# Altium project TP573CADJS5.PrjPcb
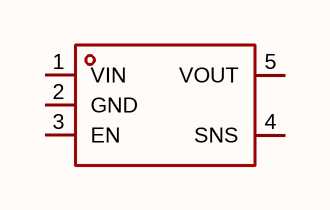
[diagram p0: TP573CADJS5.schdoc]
1 sheet, 1 parts. Net scope: global (net labels, ports and power ports of the same name join across sheets).

## Sheet TP573CADJS5.schdoc
size 127 x 101 mm

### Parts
U?  tp573cadjs5  [SOT-23-5_L2.9-W1.6-P0.95-LS2.8-BR]  (value not drawn)

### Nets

Not connected (* = marked no-connect by the designer): U? 1(VIN) 2(GND) 3(EN) 4(SNS) 5(VOUT)

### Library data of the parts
U? = tp573cadjs5: 输出极性:正极;工作电压:50V;输出电压:-;输出电流:200mA;电源纹波抑制比(PSRR):70dB@(100Hz);输出类型:可调;; Manufacturer: TECH PUBLIC(台舟); AddInBom: yes; ModelId: 7ba65df16e7b4570af156e925f9c37fe; ModelTransform: 114.173,114.173,0,90,0,0,0,0,0; Output Configuration: 正极; Voltage - Supply: 50V; Output Current: 200mA; Voltage Dropout: 660mV@(100mA); standby current: 25uA; Output Type: 可调; Number of Outputs: 1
